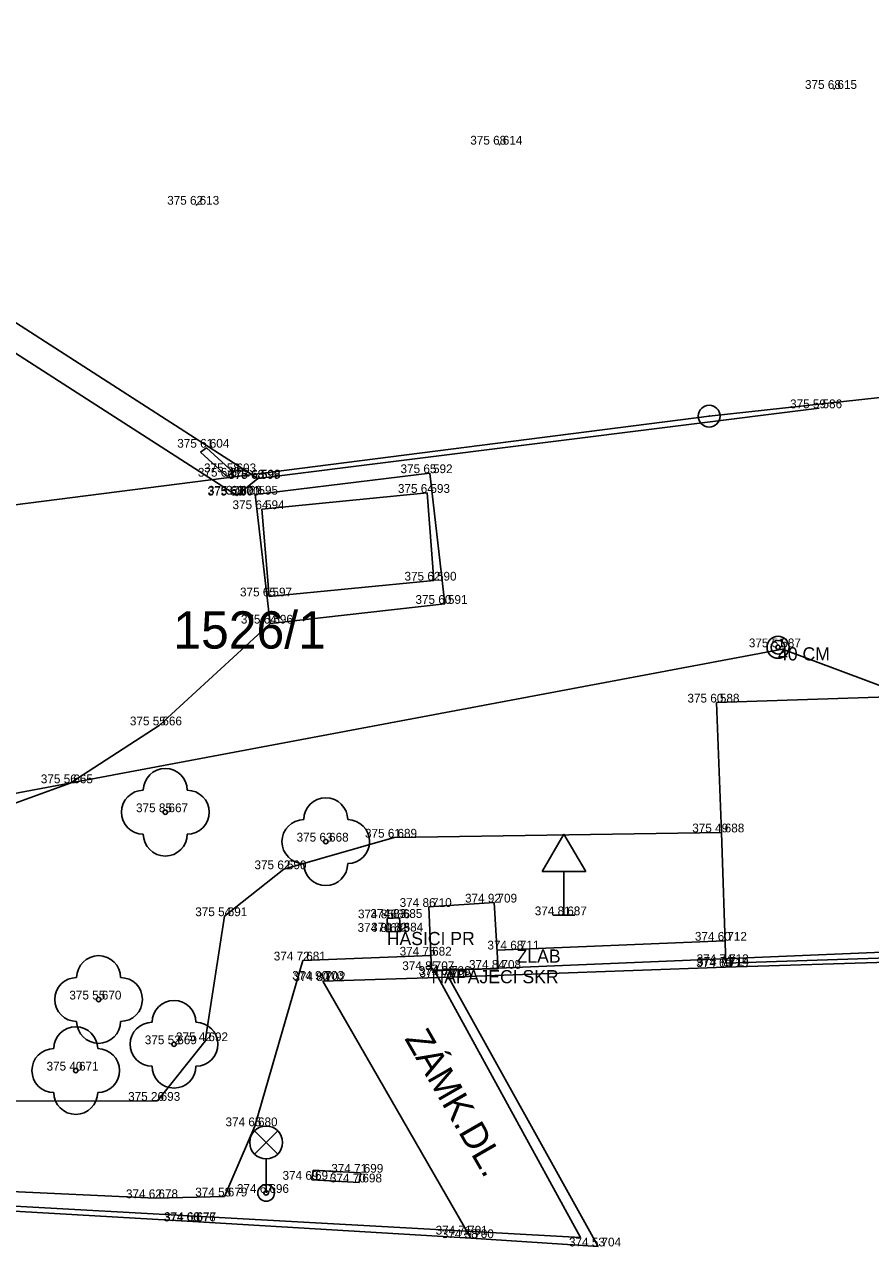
# Model space of a CAD drawing. Extents: x -601196 to -600262, y -1082523 to -1081922.
# Drawn here: x -600548.83 to -600529.54, y -1082106.57 to -1082078.71 of the extents above; entities that cross this region are included whole.
import ezdxf

# ---------------------------------------------------------------- set-up
doc = ezdxf.new("R2010")
doc.units = 0
for name, color, linetype in [('Vrstva 1', 7, 'Continuous'), ('Vrstva 10', 7, 'Continuous'), ('Vrstva 11', 7, 'Continuous'), ('Vrstva 14', 7, 'Continuous'), ('Vrstva 2', 7, 'Continuous'), ('Vrstva 20', 7, 'Continuous'), ('Vrstva 22', 7, 'Continuous'), ('Vrstva 24', 7, 'Continuous'), ('Vrstva 25', 7, 'Continuous'), ('Vrstva 3', 7, 'Continuous'), ('Vrstva 33', 7, 'Continuous'), ('Vrstva 34', 7, 'Continuous'), ('Vrstva 40', 7, 'Continuous'), ('Vrstva 47', 7, 'Continuous'), ('Vrstva 5', 7, 'Continuous'), ('Vrstva 63', 7, 'Continuous'), ('Vrstva 7', 7, 'Continuous')]:
    doc.layers.add(name, color=color, linetype=linetype)

msp = doc.modelspace()

# ---------------------------------------------------------------- linework, layer by layer
at = {"layer": 'Vrstva 1'}
for p, q in [((-600530.37, -1082080.18), (-600530.37, -1082080.18)), ((-600538, -1082081.45), (-600538, -1082081.45)), ((-600544.91, -1082082.82), (-600544.91, -1082082.82)), ((-600530.71, -1082087.46), (-600530.71, -1082087.46)), ((-600544.68, -1082088.36), (-600544.68, -1082088.36)), ((-600544.07, -1082088.92), (-600544.07, -1082088.92)), ((-600539.59, -1082088.94), (-600539.59, -1082088.94)), ((-600544.21, -1082089.02), (-600544.21, -1082089.02)), ((-600543.52, -1082089.07), (-600543.52, -1082089.07)), ((-600543.51, -1082089.06), (-600543.51, -1082089.06)), ((-600543.99, -1082089.45), (-600543.99, -1082089.45)), ((-600543.98, -1082089.43), (-600543.98, -1082089.43)), ((-600543.57, -1082089.43), (-600543.57, -1082089.43)), ((-600539.65, -1082089.39), (-600539.65, -1082089.39)), ((-600543.42, -1082089.76), (-600543.42, -1082089.76)), ((-600539.5, -1082091.39), (-600539.5, -1082091.39)), ((-600543.25, -1082091.75), (-600543.25, -1082091.75)), ((-600539.25, -1082091.92), (-600539.25, -1082091.92)), ((-600543.23, -1082092.37), (-600543.23, -1082092.37)), ((-600531.65, -1082092.91), (-600531.65, -1082092.91)), ((-600533.05, -1082094.17), (-600533.05, -1082094.17)), ((-600545.76, -1082094.69), (-600545.76, -1082094.69)), ((-600547.79, -1082096.01), (-600547.79, -1082096.01)), ((-600545.62, -1082096.67), (-600545.62, -1082096.67)), ((-600541.96, -1082097.34), (-600541.96, -1082097.34)), ((-600540.4, -1082097.25), (-600540.4, -1082097.25)), ((-600532.94, -1082097.13), (-600532.94, -1082097.13)), ((-600542.92, -1082097.97), (-600542.92, -1082097.97)), ((-600538.12, -1082098.73), (-600538.12, -1082098.73)), ((-600544.27, -1082099.04), (-600544.27, -1082099.04)), ((-600539.61, -1082098.83), (-600539.61, -1082098.83)), ((-600536.53, -1082099.02), (-600536.53, -1082099.02)), ((-600540.56, -1082099.09), (-600540.56, -1082099.09)), ((-600540.28, -1082099.08), (-600540.28, -1082099.08)), ((-600540.57, -1082099.4), (-600540.57, -1082099.4)), ((-600540.26, -1082099.39), (-600540.26, -1082099.39)), ((-600537.61, -1082099.8), (-600537.61, -1082099.8)), ((-600532.88, -1082099.6), (-600532.88, -1082099.6)), ((-600542.48, -1082100.05), (-600542.48, -1082100.05)), ((-600539.61, -1082099.94), (-600539.61, -1082099.94)), ((-600532.84, -1082100.11), (-600532.84, -1082100.11)), ((-600539.55, -1082100.27), (-600539.55, -1082100.27)), ((-600539.55, -1082100.27), (-600539.55, -1082100.27)), ((-600539.18, -1082100.38), (-600539.18, -1082100.38)), ((-600539.16, -1082100.43), (-600539.16, -1082100.43)), ((-600538.03, -1082100.24), (-600538.03, -1082100.24)), ((-600532.85, -1082100.2), (-600532.85, -1082100.2)), ((-600532.83, -1082100.17), (-600532.83, -1082100.17)), ((-600542.06, -1082100.49), (-600542.06, -1082100.49)), ((-600542.03, -1082100.52), (-600542.03, -1082100.52)), ((-600547.14, -1082100.94), (-600547.14, -1082100.94)), ((-600545.42, -1082101.96), (-600545.42, -1082101.96)), ((-600544.71, -1082101.89), (-600544.71, -1082101.89)), ((-600547.66, -1082102.56), (-600547.66, -1082102.56)), ((-600545.8, -1082103.25), (-600545.8, -1082103.25)), ((-600543.58, -1082103.83), (-600543.58, -1082103.83)), ((-600541.17, -1082104.89), (-600541.17, -1082104.89)), ((-600542.28, -1082105.05), (-600542.28, -1082105.05)), ((-600541.2, -1082105.11), (-600541.2, -1082105.11)), ((-600544.27, -1082105.43), (-600544.27, -1082105.43)), ((-600543.32, -1082105.35), (-600543.32, -1082105.35)), ((-600545.85, -1082105.47), (-600545.85, -1082105.47)), ((-600544.99, -1082106), (-600544.99, -1082106)), ((-600544.98, -1082105.99), (-600544.98, -1082105.99)), ((-600538.79, -1082106.3), (-600538.79, -1082106.3)), ((-600538.65, -1082106.38), (-600538.65, -1082106.38)), ((-600535.75, -1082106.57), (-600535.75, -1082106.57))]:
    msp.add_line(p, q, dxfattribs=at)
at = {"layer": 'Vrstva 10'}
for p, q in [((-600543.99, -1082089.45), (-600549.89, -1082085.66)), ((-600543.51, -1082089.06), (-600543.99, -1082089.45)), ((-600532.85, -1082100.2), (-600521.8, -1082099.87)), ((-600542.03, -1082100.52), (-600539.16, -1082100.43)), ((-600539.16, -1082100.43), (-600532.85, -1082100.2)), ((-600538.65, -1082106.38), (-600542.03, -1082100.52)), ((-600556.33, -1082105.35), (-600544.99, -1082106)), ((-600544.99, -1082106), (-600538.65, -1082106.38))]:
    msp.add_line(p, q, dxfattribs=at)
at = {"layer": 'Vrstva 11'}
for p, q in [((-600539.59, -1082088.94), (-600543.57, -1082089.43)), ((-600539.25, -1082091.92), (-600539.59, -1082088.94)), ((-600543.57, -1082089.43), (-600543.23, -1082092.37)), ((-600543.23, -1082092.37), (-600539.25, -1082091.92)), ((-600545.76, -1082094.69), (-600543.23, -1082092.37)), ((-600547.79, -1082096.01), (-600545.76, -1082094.69)), ((-600555.44, -1082098.78), (-600547.79, -1082096.01)), ((-600538.12, -1082098.73), (-600539.61, -1082098.83)), ((-600538.03, -1082100.24), (-600538.12, -1082098.73)), ((-600539.55, -1082100.27), (-600539.61, -1082098.83)), ((-600540.57, -1082099.4), (-600540.56, -1082099.09)), ((-600540.28, -1082099.08), (-600540.56, -1082099.09)), ((-600540.26, -1082099.39), (-600540.28, -1082099.08)), ((-600540.57, -1082099.4), (-600540.26, -1082099.39)), ((-600539.55, -1082100.27), (-600538.03, -1082100.24)), ((-600535.75, -1082106.57), (-600539.16, -1082100.43)), ((-600538.65, -1082106.38), (-600535.75, -1082106.57))]:
    msp.add_line(p, q, dxfattribs=at)
at = {"layer": 'Vrstva 14'}
for p, q in [((-600540.4, -1082097.25), (-600542.92, -1082097.97)), ((-600532.94, -1082097.13), (-600540.4, -1082097.25)), ((-600542.92, -1082097.97), (-600544.27, -1082099.04)), ((-600544.27, -1082099.04), (-600544.71, -1082101.89)), ((-600538.055, -1082099.819), (-600532.88, -1082099.6)), ((-600543.58, -1082103.83), (-600542.48, -1082100.05)), ((-600542.48, -1082100.05), (-600539.564, -1082099.938)), ((-600544.71, -1082101.89), (-600545.8, -1082103.25)), ((-600545.8, -1082103.25), (-600549.62, -1082103.26)), ((-600544.27, -1082105.43), (-600543.58, -1082103.83)), ((-600556.32, -1082104.98), (-600545.85, -1082105.47)), ((-600545.85, -1082105.47), (-600544.27, -1082105.43))]:
    msp.add_line(p, q, dxfattribs=at)
at = {"layer": 'Vrstva 20'}
for p, q in [((-600530.38, -1082080.18), (-600530.36, -1082080.18)), ((-600530.37, -1082080.165), (-600530.37, -1082080.18)), ((-600530.37, -1082080.195), (-600530.37, -1082080.18)), ((-600538.01, -1082081.45), (-600537.99, -1082081.45)), ((-600538, -1082081.435), (-600538, -1082081.45)), ((-600538, -1082081.465), (-600538, -1082081.45)), ((-600544.92, -1082082.82), (-600544.9, -1082082.82)), ((-600544.91, -1082082.805), (-600544.91, -1082082.82)), ((-600544.91, -1082082.835), (-600544.91, -1082082.82)), ((-600543.53, -1082089.07), (-600543.51, -1082089.07)), ((-600543.52, -1082089.055), (-600543.52, -1082089.07)), ((-600543.52, -1082089.085), (-600543.52, -1082089.07)), ((-600543.99, -1082089.43), (-600543.97, -1082089.43)), ((-600543.98, -1082089.415), (-600543.98, -1082089.43)), ((-600543.98, -1082089.445), (-600543.98, -1082089.43)), ((-600532.83, -1082100.155), (-600532.83, -1082100.17)), ((-600539.19, -1082100.38), (-600539.17, -1082100.38)), ((-600539.18, -1082100.365), (-600539.18, -1082100.38)), ((-600539.18, -1082100.395), (-600539.18, -1082100.38)), ((-600532.84, -1082100.17), (-600532.82, -1082100.17)), ((-600532.83, -1082100.185), (-600532.83, -1082100.17)), ((-600542.07, -1082100.49), (-600542.05, -1082100.49)), ((-600542.06, -1082100.475), (-600542.06, -1082100.49)), ((-600542.06, -1082100.505), (-600542.06, -1082100.49)), ((-600544.99, -1082105.99), (-600544.97, -1082105.99)), ((-600544.98, -1082105.975), (-600544.98, -1082105.99)), ((-600544.98, -1082106.005), (-600544.98, -1082105.99)), ((-600538.79, -1082106.285), (-600538.79, -1082106.3)), ((-600538.8, -1082106.3), (-600538.78, -1082106.3)), ((-600538.79, -1082106.315), (-600538.79, -1082106.3))]:
    msp.add_line(p, q, dxfattribs=at)
at = {"layer": 'Vrstva 22'}
for centre in [(-600545.62, -1082096.67), (-600541.96, -1082097.34), (-600547.14, -1082100.94), (-600545.42, -1082101.96), (-600547.66, -1082102.56)]:
    msp.add_circle(centre, 0.05, dxfattribs=at)
for centre, start, end in [((-600545.62, -1082096.17), 0, 180), ((-600546.12, -1082096.67), 90, 270), ((-600545.12, -1082096.67), 270, 90), ((-600541.96, -1082096.84), 0, 180), ((-600542.46, -1082097.34), 90, 270), ((-600541.46, -1082097.34), 270, 90), ((-600545.62, -1082097.17), 180, 0), ((-600541.96, -1082097.84), 180, 0), ((-600547.14, -1082100.44), 0, 180), ((-600547.64, -1082100.94), 90, 270), ((-600546.64, -1082100.94), 270, 90), ((-600545.42, -1082101.46), 0, 180), ((-600547.14, -1082101.44), 180, 0), ((-600545.92, -1082101.96), 90, 270), ((-600544.92, -1082101.96), 270, 90), ((-600547.66, -1082102.06), 0, 180), ((-600548.16, -1082102.56), 90, 270), ((-600547.16, -1082102.56), 270, 90), ((-600545.42, -1082102.46), 180, 0), ((-600547.66, -1082103.06), 180, 0)]:
    msp.add_arc(centre, 0.5, start, end, dxfattribs=at)
at = {"layer": 'Vrstva 24'}
for p, q in [((-600544.68, -1082088.36), (-600544.82, -1082088.46)), ((-600544.07, -1082088.92), (-600544.68, -1082088.36)), ((-600544.21, -1082089.02), (-600544.82, -1082088.46)), ((-600544.21, -1082089.02), (-600544.07, -1082088.92)), ((-600542.28, -1082105.05), (-600542.25, -1082104.83)), ((-600541.17, -1082104.89), (-600542.25, -1082104.83)), ((-600541.2, -1082105.11), (-600541.17, -1082104.89)), ((-600542.28, -1082105.05), (-600541.2, -1082105.11))]:
    msp.add_line(p, q, dxfattribs=at)
at = {"layer": 'Vrstva 25'}
for radius in [0.25, 0.158, 0.05]:
    msp.add_circle((-600531.65, -1082092.91), radius, dxfattribs=at)
at = {"layer": 'Vrstva 33'}
for p, q in [((-600543.585, -1082103.935), (-600543.055, -1082104.465)), ((-600543.585, -1082104.465), (-600543.055, -1082103.935)), ((-600543.32, -1082105.35), (-600543.32, -1082104.575))]:
    msp.add_line(p, q, dxfattribs=at)
for centre, radius in [((-600543.32, -1082104.2), 0.375), ((-600543.32, -1082105.35), 0.19), ((-600543.32, -1082105.35), 0.05)]:
    msp.add_circle(centre, radius, dxfattribs=at)
at = {"layer": 'Vrstva 34'}
for p, q in [((-600537.03, -1082098.02), (-600536.53, -1082097.17)), ((-600536.53, -1082097.17), (-600536.03, -1082098.02)), ((-600537.03, -1082098.02), (-600536.03, -1082098.02)), ((-600536.53, -1082099.02), (-600536.53, -1082098.02)), ((-600536.78, -1082099.02), (-600536.28, -1082099.02))]:
    msp.add_line(p, q, dxfattribs=at)
at = {"layer": 'Vrstva 47'}
for p, q in [((-600533.22, -1082087.64), (-600524.24, -1082086.66)), ((-600560.25, -1082091.09), (-600533.22, -1082087.64)), ((-600531.55, -1082092.95), (-600568.41, -1082099.89)), ((-600516.96, -1082098.42), (-600531.55, -1082092.95)), ((-600539.48, -1082100.29), (-600521.78, -1082099.55)), ((-600536.15, -1082106.37), (-600539.48, -1082100.29)), ((-600563.61, -1082104.85), (-600544.53, -1082105.9)), ((-600544.53, -1082105.9), (-600536.15, -1082106.37))]:
    msp.add_line(p, q, dxfattribs=at)
for radius in [0.25, 0.005]:
    msp.add_circle((-600533.22, -1082087.64), radius, dxfattribs=at)
at = {"layer": 'Vrstva 5'}
for p, q in [((-600539.65, -1082089.39), (-600543.42, -1082089.76)), ((-600539.5, -1082091.39), (-600539.65, -1082089.39)), ((-600543.42, -1082089.76), (-600543.25, -1082091.75)), ((-600539.5, -1082091.39), (-600543.25, -1082091.75)), ((-600522.06, -1082093.81), (-600533.05, -1082094.17)), ((-600533.05, -1082094.17), (-600532.94, -1082097.13)), ((-600532.94, -1082097.13), (-600532.84, -1082100.11)), ((-600532.84, -1082100.11), (-600521.85, -1082099.76))]:
    msp.add_line(p, q, dxfattribs=at)
at = {"layer": 'Vrstva 7'}
for p, q in [((-600543.51, -1082089.06), (-600559.62, -1082078.71)), ((-600530.71, -1082087.46), (-600543.51, -1082089.06))]:
    msp.add_line(p, q, dxfattribs=at)

# ---------------------------------------------------------------- texts
at = {"layer": 'Vrstva 2'}
for s, p in [(' 615', (-600530.37, -1082080.18)), (' 614', (-600538, -1082081.45)), (' 613', (-600544.91, -1082082.82)), (' 586', (-600530.71, -1082087.46)), (' 604', (-600544.68, -1082088.36)), (' 603', (-600544.07, -1082088.92)), (' 602', (-600544.21, -1082089.02)), (' 599', (-600543.52, -1082089.07)), (' 598', (-600543.51, -1082089.06)), (' 592', (-600539.59, -1082088.94)), (' 600', (-600543.99, -1082089.45)), (' 601', (-600543.98, -1082089.43)), (' 595', (-600543.57, -1082089.43)), (' 593', (-600539.65, -1082089.39)), (' 594', (-600543.42, -1082089.76)), (' 590', (-600539.5, -1082091.39)), (' 597', (-600543.25, -1082091.75)), (' 591', (-600539.25, -1082091.92)), (' 596', (-600543.23, -1082092.37)), (' 587', (-600531.65, -1082092.91)), (' 588', (-600533.05, -1082094.17)), (' 666', (-600545.76, -1082094.69)), (' 665', (-600547.79, -1082096.01)), (' 667', (-600545.62, -1082096.67)), (' 689', (-600540.4, -1082097.25)), (' 688', (-600532.94, -1082097.13)), (' 668', (-600541.96, -1082097.34)), (' 690', (-600542.92, -1082097.97)), (' 710', (-600539.61, -1082098.83)), (' 709', (-600538.12, -1082098.73)), (' 691', (-600544.27, -1082099.04)), (' 686', (-600540.56, -1082099.09)), (' 685', (-600540.28, -1082099.08)), (' 687', (-600536.53, -1082099.02)), (' 683', (-600540.57, -1082099.4)), (' 684', (-600540.26, -1082099.39)), (' 712', (-600532.88, -1082099.6)), (' 681', (-600542.48, -1082100.05)), (' 682', (-600539.61, -1082099.94)), (' 711', (-600537.61, -1082099.8)), (' 707', (-600539.55, -1082100.27)), (' 707', (-600539.55, -1082100.27)), (' 708', (-600538.03, -1082100.24)), (' 715', (-600532.85, -1082100.2)), (' 713', (-600532.84, -1082100.11)), (' 714', (-600532.83, -1082100.17)), (' 703', (-600542.06, -1082100.49)), (' 702', (-600542.03, -1082100.52)), (' 706', (-600539.18, -1082100.38)), (' 705', (-600539.16, -1082100.43)), (' 670', (-600547.14, -1082100.94)), (' 669', (-600545.42, -1082101.96)), (' 692', (-600544.71, -1082101.89)), (' 671', (-600547.66, -1082102.56)), (' 693', (-600545.8, -1082103.25)), (' 680', (-600543.58, -1082103.83)), (' 697', (-600542.28, -1082105.05)), (' 699', (-600541.17, -1082104.89)), (' 696', (-600543.32, -1082105.35)), (' 698', (-600541.2, -1082105.11)), (' 678', (-600545.85, -1082105.47)), (' 679', (-600544.27, -1082105.43)), (' 676', (-600544.99, -1082106)), (' 677', (-600544.98, -1082105.99)), (' 701', (-600538.79, -1082106.3)), (' 700', (-600538.65, -1082106.38)), (' 704', (-600535.75, -1082106.57))]:
    msp.add_text(s, height=0.2, dxfattribs=at).set_placement(p)
at = {"layer": 'Vrstva 3'}
for s, p in [('375 68 ', (-600531.036, -1082080.18)), ('375 68 ', (-600538.666, -1082081.45)), ('375 62 ', (-600545.576, -1082082.82)), ('375 59 ', (-600531.376, -1082087.46)), ('375 61 ', (-600545.346, -1082088.36)), ('375 58 ', (-600544.736, -1082088.92)), ('375 64 ', (-600544.876, -1082089.02)), ('375 68 ', (-600544.186, -1082089.07)), ('375 63 ', (-600544.176, -1082089.06)), ('375 65 ', (-600540.256, -1082088.94)), ('375 58 ', (-600544.656, -1082089.45)), ('375 69 ', (-600544.646, -1082089.43)), ('375 69 ', (-600544.236, -1082089.43)), ('375 64 ', (-600540.316, -1082089.39)), ('375 64 ', (-600544.086, -1082089.76)), ('375 62 ', (-600540.166, -1082091.39)), ('375 65 ', (-600543.916, -1082091.75)), ('375 60 ', (-600539.916, -1082091.92)), ('375 64 ', (-600543.896, -1082092.37)), ('375 51 ', (-600532.316, -1082092.91)), ('375 60 ', (-600533.716, -1082094.17)), ('375 55 ', (-600546.426, -1082094.69)), ('375 56 ', (-600548.456, -1082096.01)), ('375 85 ', (-600546.286, -1082096.67)), ('375 61 ', (-600541.066, -1082097.25)), ('375 49 ', (-600533.606, -1082097.13)), ('375 63 ', (-600542.626, -1082097.34)), ('375 62 ', (-600543.586, -1082097.97)), ('374 86 ', (-600540.276, -1082098.83)), ('374 92 ', (-600538.786, -1082098.73)), ('375 54 ', (-600544.936, -1082099.04)), ('374 85 ', (-600541.226, -1082099.09)), ('374 83 ', (-600540.946, -1082099.08)), ('374 81 ', (-600537.196, -1082099.02)), ('374 81 ', (-600541.236, -1082099.4)), ('374 82 ', (-600540.926, -1082099.39)), ('374 68 ', (-600538.276, -1082099.8)), ('374 60 ', (-600533.546, -1082099.6)), ('374 72 ', (-600543.146, -1082100.05)), ('374 75 ', (-600540.276, -1082099.94)), ('374 85 ', (-600540.216, -1082100.27)), ('374 85 ', (-600540.216, -1082100.27)), ('374 84 ', (-600538.696, -1082100.24)), ('374 60 ', (-600533.516, -1082100.2)), ('374 74 ', (-600533.506, -1082100.11)), ('374 71 ', (-600533.496, -1082100.17)), ('374 90 ', (-600542.726, -1082100.49)), ('374 80 ', (-600542.696, -1082100.52)), ('374 86 ', (-600539.846, -1082100.38)), ('374 76 ', (-600539.826, -1082100.43)), ('375 55 ', (-600547.806, -1082100.94)), ('375 52 ', (-600546.086, -1082101.96)), ('375 42 ', (-600545.376, -1082101.89)), ('375 40 ', (-600548.326, -1082102.56)), ('375 26 ', (-600546.466, -1082103.25)), ('374 65 ', (-600544.246, -1082103.83)), ('374 69 ', (-600542.946, -1082105.05)), ('374 71 ', (-600541.836, -1082104.89)), ('374 67 ', (-600543.986, -1082105.35)), ('374 70 ', (-600541.866, -1082105.11)), ('374 62 ', (-600546.516, -1082105.47)), ('374 58 ', (-600544.936, -1082105.43)), ('374 60 ', (-600545.656, -1082106)), ('374 68 ', (-600545.646, -1082105.99)), ('374 71 ', (-600539.456, -1082106.3)), ('374 58 ', (-600539.316, -1082106.38)), ('374 53 ', (-600536.416, -1082106.57))]:
    msp.add_text(s, height=0.2, dxfattribs=at).set_placement(p)
at = {"layer": 'Vrstva 40'}
msp.add_text('ZÁMK.DL.', height=0.6, rotation=299.976, dxfattribs=at).set_placement((-600540.175, -1082101.833))
at = {"layer": 'Vrstva 47'}
msp.add_text('1526/1', height=0.85, dxfattribs=at).set_placement((-600545.436, -1082092.94))
at = {"layer": 'Vrstva 63'}
for s, p in [('40 CM', (-600531.65, -1082093.21)), ('HASICI PR', (-600540.57, -1082099.7)), ('ZLAB', (-600537.61, -1082100.1)), ('NAPAJECI SKR', (-600539.55, -1082100.57))]:
    msp.add_text(s, height=0.3, dxfattribs=at).set_placement(p)

doc.saveas('drawing.dxf')
